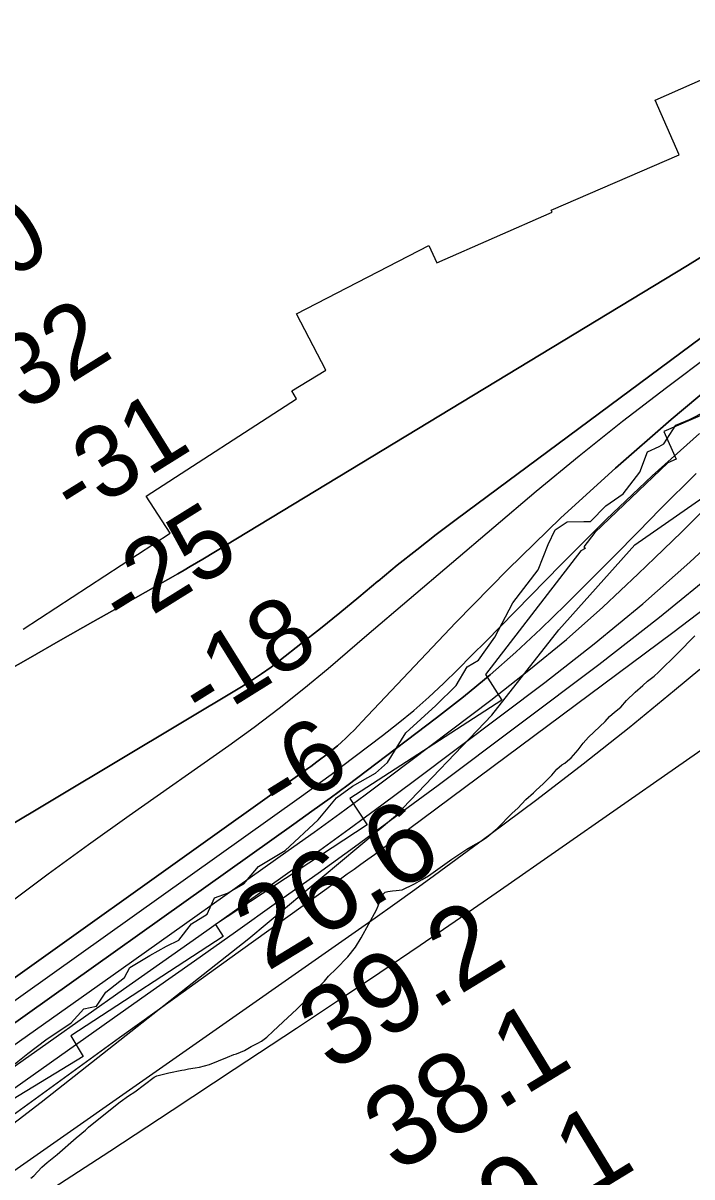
# Model space of a CAD drawing. Extents: x 3245246 to 3283090, y 806824 to 832173.
# Drawn here: x 3257079 to 3257636, y 817086 to 818047 of the extents above; entities that cross this region are included whole.
import ezdxf

# ---------------------------------------------------------------- set-up
doc = ezdxf.new("R2010")
doc.units = 0
for name, color, linetype in [('V-RIVR-EDGE', 7, 'Continuous'), ('V-RIVR-RANG', 7, 'Continuous'), ('V-RRAP-FSHR', 7, 'Continuous'), ('V-RRAP-RVMT', 7, 'Continuous'), ('V-SITE-VEGE', 7, 'Continuous'), ('V-TOPO-DPTH', 7, 'Continuous'), ('V-TOPO-MAJR', 7, 'Continuous'), ('V-TOPO-MINR', 7, 'Continuous'), ('V-TOPO-WATR', 7, 'Continuous')]:
    doc.layers.add(name, color=color, linetype=linetype)

msp = doc.modelspace()

# ---------------------------------------------------------------- linework, layer by layer
at = {"layer": 'V-RIVR-EDGE'}
msp.add_lwpolyline([(3257050.39, 817162.97), (3257082.62, 817188.53), (3257097.42, 817199.8), (3257118.76, 817214.09), (3257129.22, 817225.8), (3257139.66, 817227.95), (3257147.51, 817239.66), (3257163.19, 817251.8), (3257167.56, 817260.04), (3257184.1, 817270), (3257198.03, 817277.79), (3257208.47, 817282.98), (3257218.94, 817296.43), (3257232, 817304.66), (3257238.12, 817318.12), (3257248.99, 817322), (3257262.49, 817329.79), (3257274.69, 817344.11), (3257296.9, 817357.53), (3257324.34, 817383.1), (3257339.6, 817401.32), (3257353.1, 817411.29), (3257372.26, 817422.11), (3257382.27, 817430.78), (3257397.55, 817455.52), (3257422.38, 817478.49), (3257439.38, 817494.97), (3257448.54, 817510.59), (3257458.12, 817516.22), (3257471.64, 817535.31), (3257486.49, 817563.97), (3257507.86, 817591.3), (3257516.17, 817612.58), (3257521.85, 817624.73), (3257531.87, 817631.23), (3257545.78, 817631.63), (3257551.43, 817631.61), (3257564.06, 817644.62), (3257578.43, 817654.59), (3257592.39, 817672.81), (3257598.95, 817689.74), (3257608.52, 817694.07), (3257612.44, 817696.23), (3257622.48, 817711.85), (3257633.79, 817716.61), (3257647.28, 817723.53)], dxfattribs=at)
at = {"layer": 'V-RRAP-FSHR'}
msp.add_lwpolyline([(3256099.77, 816503.61), (3256421.07, 816695.99), (3256733.82, 816893.19), (3256847.59, 816962.01), (3256970.02, 817053.28), (3257093.64, 817147.99), (3257266.71, 817284.24), (3257388.92, 817386.59), (3257469.01, 817470.23), (3257525.08, 817541.48), (3257588.22, 817612.14), (3257698.7, 817688.97), (3257767.04, 817744.55), (3257833, 817785.65), (3257894.35, 817818.31), (3257965.18, 817866.85), (3258034.99, 817924.36), (3258124.19, 817980.78), (3258147.2, 817993.46)], dxfattribs=at)
at = {"layer": 'V-RRAP-RVMT'}
for p, q in [((3257605.21, 817982.49), (3257710.53, 818029.16)), ((3257605.21, 817982.49), (3257710.53, 818029.16)), ((3257625.08, 817936.98), (3257605.21, 817982.49)), ((3257625.08, 817936.98), (3257605.21, 817982.49)), ((3257518.52, 817890.95), (3257625.08, 817936.98)), ((3257518.52, 817890.95), (3257625.08, 817936.98)), ((3257423.4, 817847.07), (3257519.28, 817889.2)), ((3257423.4, 817847.07), (3257519.28, 817889.2)), ((3257519.28, 817889.2), (3257518.52, 817890.95)), ((3257519.28, 817889.2), (3257518.52, 817890.95)), ((3257306.51, 817804.74), (3257416.54, 817861.44)), ((3257306.51, 817804.74), (3257416.54, 817861.44)), ((3257416.54, 817861.44), (3257423.4, 817847.07)), ((3257416.54, 817861.44), (3257423.4, 817847.07)), ((3257330.72, 817757.7), (3257306.51, 817804.74)), ((3257330.72, 817757.7), (3257306.51, 817804.74)), ((3257302.46, 817740.41), (3257330.72, 817757.7)), ((3257302.46, 817740.41), (3257330.72, 817757.7)), ((3257718, 817752.6), (3257612.5, 817706.64)), ((3257718, 817752.6), (3257612.5, 817706.64)), ((3257306.42, 817733.91), (3257302.46, 817740.41)), ((3257306.42, 817733.91), (3257302.46, 817740.41)), ((3257181.27, 817652.62), (3257306.42, 817733.91)), ((3257181.27, 817652.62), (3257306.42, 817733.91)), ((3257612.5, 817706.64), (3257622.58, 817683.52)), ((3257612.5, 817706.64), (3257622.58, 817683.52)), ((3257622.58, 817683.52), (3257615.67, 817680.43)), ((3257622.58, 817683.52), (3257615.67, 817680.43)), ((3257615.67, 817680.43), (3257555.08, 817622.53)), ((3257615.67, 817680.43), (3257555.08, 817622.53)), ((3257201.02, 817621.88), (3257181.27, 817652.62)), ((3257201.02, 817621.88), (3257181.27, 817652.62)), ((3257078.59, 817541.9), (3257201.02, 817621.88)), ((3257078.59, 817541.9), (3257201.02, 817621.88)), ((3257555.08, 817622.53), (3257545.91, 817610.64)), ((3257555.08, 817622.53), (3257545.91, 817610.64)), ((3257543.32, 817607.27), (3257463.75, 817504.06)), ((3257543.32, 817607.27), (3257463.75, 817504.06)), ((3257546.78, 817609.05), (3257543.32, 817607.27)), ((3257546.78, 817609.05), (3257543.32, 817607.27)), ((3257545.91, 817610.64), (3257546.78, 817609.05)), ((3257545.91, 817610.64), (3257546.78, 817609.05)), ((3257463.75, 817504.06), (3257477.4, 817482.91)), ((3257463.75, 817504.06), (3257477.4, 817482.91)), ((3257477.4, 817482.91), (3257350.75, 817401.01)), ((3257477.4, 817482.91), (3257350.75, 817401.01)), ((3257350.75, 817401.01), (3257365.25, 817379.09)), ((3257350.75, 817401.01), (3257365.25, 817379.09)), ((3257365.25, 817379.09), (3257238.83, 817296.03)), ((3257365.25, 817379.09), (3257238.83, 817296.03)), ((3257238.83, 817296.03), (3257245.23, 817285.96)), ((3257238.83, 817296.03), (3257245.23, 817285.96)), ((3257245.23, 817285.96), (3257118.28, 817203.29)), ((3257245.23, 817285.96), (3257118.28, 817203.29)), ((3257118.28, 817203.29), (3257128.79, 817185.93)), ((3257118.28, 817203.29), (3257128.79, 817185.93)), ((3257128.79, 817185.93), (3256999.3, 817107.86)), ((3257128.79, 817185.93), (3256999.3, 817107.86))]:
    msp.add_line(p, q, dxfattribs=at)
at = {"layer": 'V-SITE-VEGE'}
for points in [[(3257145.92, 817137.5), (3257159.54, 817148.11), (3257166.45, 817153.11), (3257171.75, 817156.66), (3257187.81, 817168.73), (3257189.92, 817169.99), (3257200.12, 817172.32), (3257210.76, 817174.69), (3257213.01, 817174.92), (3257216.28, 817175.57), (3257222.01, 817176.66), (3257225.49, 817177.11), (3257233.88, 817179.26), (3257248.78, 817185.37), (3257254.08, 817187.69), (3257256.54, 817188.33), (3257263.07, 817191.07), (3257265.92, 817192.54), (3257268.57, 817194.41), (3257274.28, 817197.14), (3257277.13, 817198.81), (3257281.81, 817202.15), (3257286.88, 817207.12), (3257299.06, 817218.34), (3257302.51, 817221.66), (3257306.97, 817225.6), (3257312.85, 817231.41), (3257321.98, 817240.74), (3257329.68, 817248.62), (3257333.12, 817252.76), (3257339.41, 817258.98), (3257349.14, 817269.14), (3257355.61, 817277), (3257360.24, 817284.85), (3257373.1, 817308.16), (3257374.5, 817311.46), (3257376.28, 817316.81), (3257378.09, 817320.52), (3257380.32, 817322.8), (3257382.36, 817323.44), (3257386.25, 817324.1), (3257389.33, 817324.13), (3257394.45, 817324.81), (3257404.03, 817329.63), (3257411.16, 817333.4), (3257416.46, 817336.54), (3257435.78, 817350.49), (3257448.41, 817358.63), (3257453.5, 817361.77), (3257460.43, 817365.74), (3257464.9, 817368.66), (3257473.64, 817375.94), (3257486, 817388.58), (3257490.67, 817392.94), (3257497.57, 817399.99), (3257503.86, 817405.6), (3257506.09, 817407.88), (3257511.77, 817413.07), (3257517.05, 817418.25), (3257519.07, 817420.33), (3257523.32, 817425.3), (3257527.38, 817429.03), (3257529.83, 817430.29), (3257532.27, 817432.37), (3257535.32, 817434.66), (3257541.19, 817441.49), (3257545.23, 817446.87), (3257549.68, 817452.05), (3257563.48, 817464.91), (3257567.13, 817469.06), (3257571.39, 817472.8), (3257576.47, 817476.95), (3257581.33, 817482.54), (3257588.63, 817489.6), (3257594.93, 817495), (3257598.79, 817498.53), (3257604.27, 817502.9), (3257607.93, 817506.22), (3257623.75, 817521.57), (3257638.14, 817536.5)], [(3257084.99, 817084.73), (3257087.43, 817086.61), (3257094.33, 817093.66), (3257098.79, 817097.6), (3257107.12, 817104.26), (3257122.76, 817118.17), (3257130.68, 817124.62), (3257133.12, 817127.11), (3257145.92, 817137.5)]]:
    msp.add_lwpolyline(points, dxfattribs=at)
at = {"layer": 'V-TOPO-DPTH'}
for points in [[(3256853.29, 817250.06), (3257260.58, 817493.94), (3257268.97, 817499.18), (3257277.21, 817504.63), (3257285.25, 817510.38), (3257293.14, 817516.34), (3257310.09, 817529.64), (3257326.28, 817542.49), (3257342.39, 817555.45), (3257358.36, 817568.57), (3257374.24, 817581.81), (3257374.36, 817581.91), (3257390.35, 817595.12), (3257406.51, 817608.14), (3257422.89, 817620.85), (3257439.44, 817633.37), (3257822.31, 817917.42), (3257839.25, 817929.8), (3257856.3, 817942.03), (3257873.52, 817954.02), (3257890.85, 817965.84), (3257956.95, 818010.27), (3258007.61, 818043.89), (3258058.54, 818077.1)], [(3258058.54, 818077.1), (3258007.61, 818043.89), (3257956.95, 818010.27), (3257890.85, 817965.84), (3257873.52, 817954.02), (3257856.3, 817942.03), (3257839.25, 817929.8), (3257822.31, 817917.42), (3257439.44, 817633.37), (3257422.89, 817620.85), (3257406.51, 817608.14), (3257390.35, 817595.12), (3257374.36, 817581.91), (3257374.24, 817581.81), (3257358.36, 817568.57), (3257342.39, 817555.45), (3257326.28, 817542.49), (3257310.09, 817529.64), (3257293.14, 817516.34), (3257285.25, 817510.38), (3257277.21, 817504.63), (3257268.97, 817499.18), (3257260.58, 817493.94), (3256853.29, 817250.06)], [(3257055.72, 817501.89), (3257082.73, 817517.3), (3257109.75, 817532.69), (3257136.79, 817548.04), (3257163.84, 817563.37), (3257207.52, 817588.09), (3257212.73, 817591.07), (3257217.92, 817594.08), (3257223.09, 817597.13), (3257228.23, 817600.22), (3257632.11, 817844.94), (3257666.47, 817866.27)], [(3257666.47, 817866.27), (3257632.11, 817844.94), (3257228.23, 817600.22), (3257223.09, 817597.13), (3257217.92, 817594.08), (3257212.73, 817591.07), (3257207.52, 817588.09), (3257163.84, 817563.37), (3257136.79, 817548.04), (3257109.75, 817532.69), (3257082.73, 817517.3), (3257055.72, 817501.89)], [(3257685.18, 817772.41), (3257618.65, 817716.55), (3257572.1, 817676.08), (3257526.52, 817634.59), (3257482.4, 817591.56), (3257439.24, 817547.5), (3257360.94, 817464.77), (3257357.64, 817461.32), (3257354.3, 817457.91), (3257350.92, 817454.54), (3257347.51, 817451.2), (3257344.02, 817447.94), (3257340.46, 817444.78), (3257336.79, 817441.74), (3257333.04, 817438.79), (3257323.31, 817431.4), (3257320.79, 817429.51), (3257318.27, 817427.64), (3257315.73, 817425.79), (3257313.18, 817423.95), (3256670.1, 816965.15)], [(3256670.1, 816965.15), (3257313.18, 817423.95), (3257315.73, 817425.79), (3257318.27, 817427.64), (3257320.79, 817429.51), (3257323.31, 817431.4), (3257333.04, 817438.79), (3257336.79, 817441.74), (3257340.46, 817444.78), (3257344.02, 817447.94), (3257347.51, 817451.2), (3257350.92, 817454.54), (3257354.3, 817457.91), (3257357.64, 817461.32), (3257360.94, 817464.77), (3257439.24, 817547.5), (3257482.4, 817591.56), (3257526.52, 817634.59), (3257572.1, 817676.08), (3257618.65, 817716.55), (3257685.18, 817772.41)], [(3257639.44, 817671.65), (3257609.64, 817642.2), (3257591.05, 817623.13), (3257570.99, 817602.72), (3257550.8, 817582.44), (3257530.44, 817562.33), (3257509.96, 817542.35), (3257489.05, 817522.85), (3257467.69, 817503.87), (3257445.65, 817485.69), (3257423.16, 817468.04), (3257364.42, 817423.63), (3257349.45, 817412.41), (3257334.41, 817401.29), (3257319.28, 817390.29), (3257304.08, 817379.38), (3257027.14, 817182.44)], [(3257639.44, 817671.65), (3257609.64, 817642.2), (3257591.05, 817623.13), (3257570.99, 817602.72), (3257550.8, 817582.44), (3257530.44, 817562.33), (3257509.96, 817542.35), (3257489.05, 817522.85), (3257467.69, 817503.87), (3257445.65, 817485.69), (3257423.16, 817468.04), (3257364.42, 817423.63), (3257349.45, 817412.41), (3257334.41, 817401.29), (3257319.28, 817390.29), (3257304.08, 817379.38), (3257027.14, 817182.44)], [(3257036.69, 817153.57), (3257099.56, 817197.73), (3257162.35, 817242), (3257225.08, 817286.34), (3257295.11, 817335.92), (3257322.71, 817355.64), (3257350.2, 817375.52), (3257377.51, 817395.64), (3257404.71, 817415.91), (3257513.22, 817497.53), (3257554.47, 817529.78), (3257594.87, 817563.01), (3257634.02, 817597.73), (3257672.31, 817633.43)]]:
    msp.add_lwpolyline(points, dxfattribs=at)
at = {"layer": 'V-TOPO-MAJR'}
msp.add_lwpolyline([(3257065.29, 817086.83), (3257355.25, 817289.77), (3257371.87, 817301.48), (3257388.42, 817313.25), (3257404.91, 817325.14), (3257421.34, 817337.09), (3257467.38, 817370.81), (3257506.51, 817400.04), (3257545.28, 817429.74), (3257583.48, 817460.16), (3257621.31, 817491.05), (3257642.53, 817508.71)], dxfattribs=at)
at = {"layer": 'V-TOPO-MINR'}
for points in [[(3256853.29, 817250.06), (3257260.58, 817493.94), (3257268.97, 817499.18), (3257277.21, 817504.63), (3257285.25, 817510.38), (3257293.14, 817516.34), (3257310.09, 817529.64), (3257326.28, 817542.49), (3257342.39, 817555.45), (3257358.36, 817568.57), (3257374.24, 817581.81), (3257374.36, 817581.91), (3257390.35, 817595.12), (3257406.51, 817608.14), (3257422.89, 817620.85), (3257439.44, 817633.37), (3257822.31, 817917.42), (3257839.25, 817929.8), (3257856.3, 817942.03), (3257873.52, 817954.02), (3257890.85, 817965.84), (3257956.95, 818010.27), (3258007.61, 818043.89), (3258058.54, 818077.1)], [(3257055.72, 817501.89), (3257082.73, 817517.3), (3257109.75, 817532.69), (3257136.79, 817548.04), (3257163.84, 817563.37), (3257207.52, 817588.09), (3257212.73, 817591.07), (3257217.92, 817594.08), (3257223.09, 817597.13), (3257228.23, 817600.22), (3257632.11, 817844.94), (3257666.47, 817866.27)], [(3256670.1, 816965.15), (3257313.18, 817423.95), (3257315.73, 817425.79), (3257318.27, 817427.64), (3257320.79, 817429.51), (3257323.31, 817431.4), (3257333.04, 817438.79), (3257336.79, 817441.74), (3257340.46, 817444.78), (3257344.02, 817447.94), (3257347.51, 817451.2), (3257350.92, 817454.54), (3257354.3, 817457.91), (3257357.64, 817461.32), (3257360.94, 817464.77), (3257439.24, 817547.5), (3257482.4, 817591.56), (3257526.52, 817634.59), (3257572.1, 817676.08), (3257618.65, 817716.55), (3257685.18, 817772.41)], [(3257066.16, 817313.28), (3257099.54, 817338.09), (3257133.22, 817362.51), (3257167.09, 817386.66), (3257249.89, 817444.99), (3257271.11, 817460.38), (3257292.03, 817476.17), (3257312.5, 817492.53), (3257332.67, 817509.29), (3257365.09, 817537), (3257400.29, 817567.02), (3257435.53, 817597.01), (3257470.82, 817626.92), (3257506.15, 817656.8), (3257541.81, 817686.24), (3257577.89, 817715.16), (3257614.59, 817743.29), (3257651.7, 817770.89)], [(3256848.55, 817073.83), (3257308.62, 817401.55), (3257317.52, 817407.95), (3257326.38, 817414.4), (3257335.18, 817420.93), (3257343.95, 817427.51), (3257378.1, 817453.38), (3257391.22, 817463.7), (3257404.08, 817474.32), (3257416.54, 817485.4), (3257428.75, 817496.78), (3257440.7, 817508.44), (3257452.59, 817520.18), (3257464.37, 817532.01), (3257476.09, 817543.92), (3257526.77, 817595.9), (3257564.36, 817633.22), (3257602.73, 817669.68), (3257642.27, 817704.87)], [(3257069.08, 817194.17), (3257160.33, 817258.66), (3257299.58, 817357.48), (3257321.01, 817372.84), (3257342.36, 817388.31), (3257363.57, 817403.98), (3257384.69, 817419.76), (3257468.2, 817482.74), (3257500.06, 817507.71), (3257531.28, 817533.43), (3257561.54, 817560.29), (3257591.15, 817587.9), (3257605.01, 817601.31), (3257627.11, 817622.87), (3257649.07, 817644.57)], [(3257036.69, 817153.57), (3257099.56, 817197.73), (3257162.35, 817242), (3257225.08, 817286.34), (3257295.11, 817335.92), (3257322.71, 817355.64), (3257350.2, 817375.52), (3257377.51, 817395.64), (3257404.71, 817415.91), (3257513.22, 817497.53), (3257554.47, 817529.78), (3257594.87, 817563.01), (3257634.02, 817597.73), (3257672.31, 817633.43)], [(3256564.99, 816800.8), (3257152.91, 817217.34), (3257187.11, 817241.56), (3257221.32, 817265.77), (3257255.54, 817289.96), (3257289.77, 817314.14), (3257290.7, 817314.8), (3257324.37, 817338.78), (3257357.9, 817362.96), (3257391.21, 817387.43), (3257424.39, 817412.08), (3257558.2, 817512.41), (3257608.84, 817551.89), (3257658.44, 817592.61)], [(3257067.23, 817135.26), (3257113.11, 817168.51), (3257159.02, 817201.72), (3257204.97, 817234.86), (3257250.96, 817267.95), (3257331.65, 817325.93), (3257337.33, 817330), (3257343.01, 817334.05), (3257348.7, 817338.09), (3257354.4, 817342.11), (3257360.09, 817346.15), (3257365.76, 817350.22), (3257371.4, 817354.33), (3257377.02, 817358.47), (3257620.05, 817539.08), (3257674.25, 817580.64)], [(3257098.79, 817073.16), (3257150.8, 817107.1), (3257202.74, 817141.15), (3257254.58, 817175.36), (3257306.35, 817209.67), (3257342.13, 817233.47), (3257375.88, 817256.08), (3257409.53, 817278.84), (3257443.03, 817301.81), (3257476.43, 817324.94), (3257670.68, 817460.43)]]:
    msp.add_lwpolyline(points, dxfattribs=at)
at = {"layer": 'V-TOPO-WATR'}
msp.add_lwpolyline([(3257027.14, 817182.44), (3257304.08, 817379.38), (3257319.28, 817390.29), (3257334.41, 817401.29), (3257349.45, 817412.41), (3257364.42, 817423.63), (3257423.16, 817468.04), (3257445.65, 817485.69), (3257467.69, 817503.87), (3257489.05, 817522.85), (3257509.96, 817542.35), (3257530.44, 817562.33), (3257550.8, 817582.44), (3257570.99, 817602.72), (3257591.05, 817623.13), (3257609.64, 817642.2), (3257639.44, 817671.65)], dxfattribs=at)

# ---------------------------------------------------------------- texts
at = {"layer": 'V-RIVR-RANG'}
for s, height, rotation, p in [('-30', 60, 31.90931, (3257006.47, 817794.49)), ('-32', 60, 31.90931, (3257057.35, 817708.38)), ('-31', 60, 31.90931, (3257122.27, 817631)), ('-25', 60, 31.90931, (3257163.13, 817538.64)), ('-18', 60, 31.90931, (3257229.05, 817461.89)), ('-6', 60, 31.90931, (3257293.37, 817384.14)), ('26.6', 67, 31.38833, (3257281.85, 817256.34)), ('39.2', 67, 31.38833, (3257335.71, 817172.06)), ('38.1', 67, 31.38833, (3257390.02, 817088.05)), ('39.1', 67, 31.38833, (3257442.31, 817002.81))]:
    msp.add_text(s, height=height, rotation=rotation, dxfattribs=at).set_placement(p)

doc.saveas('drawing.dxf')
